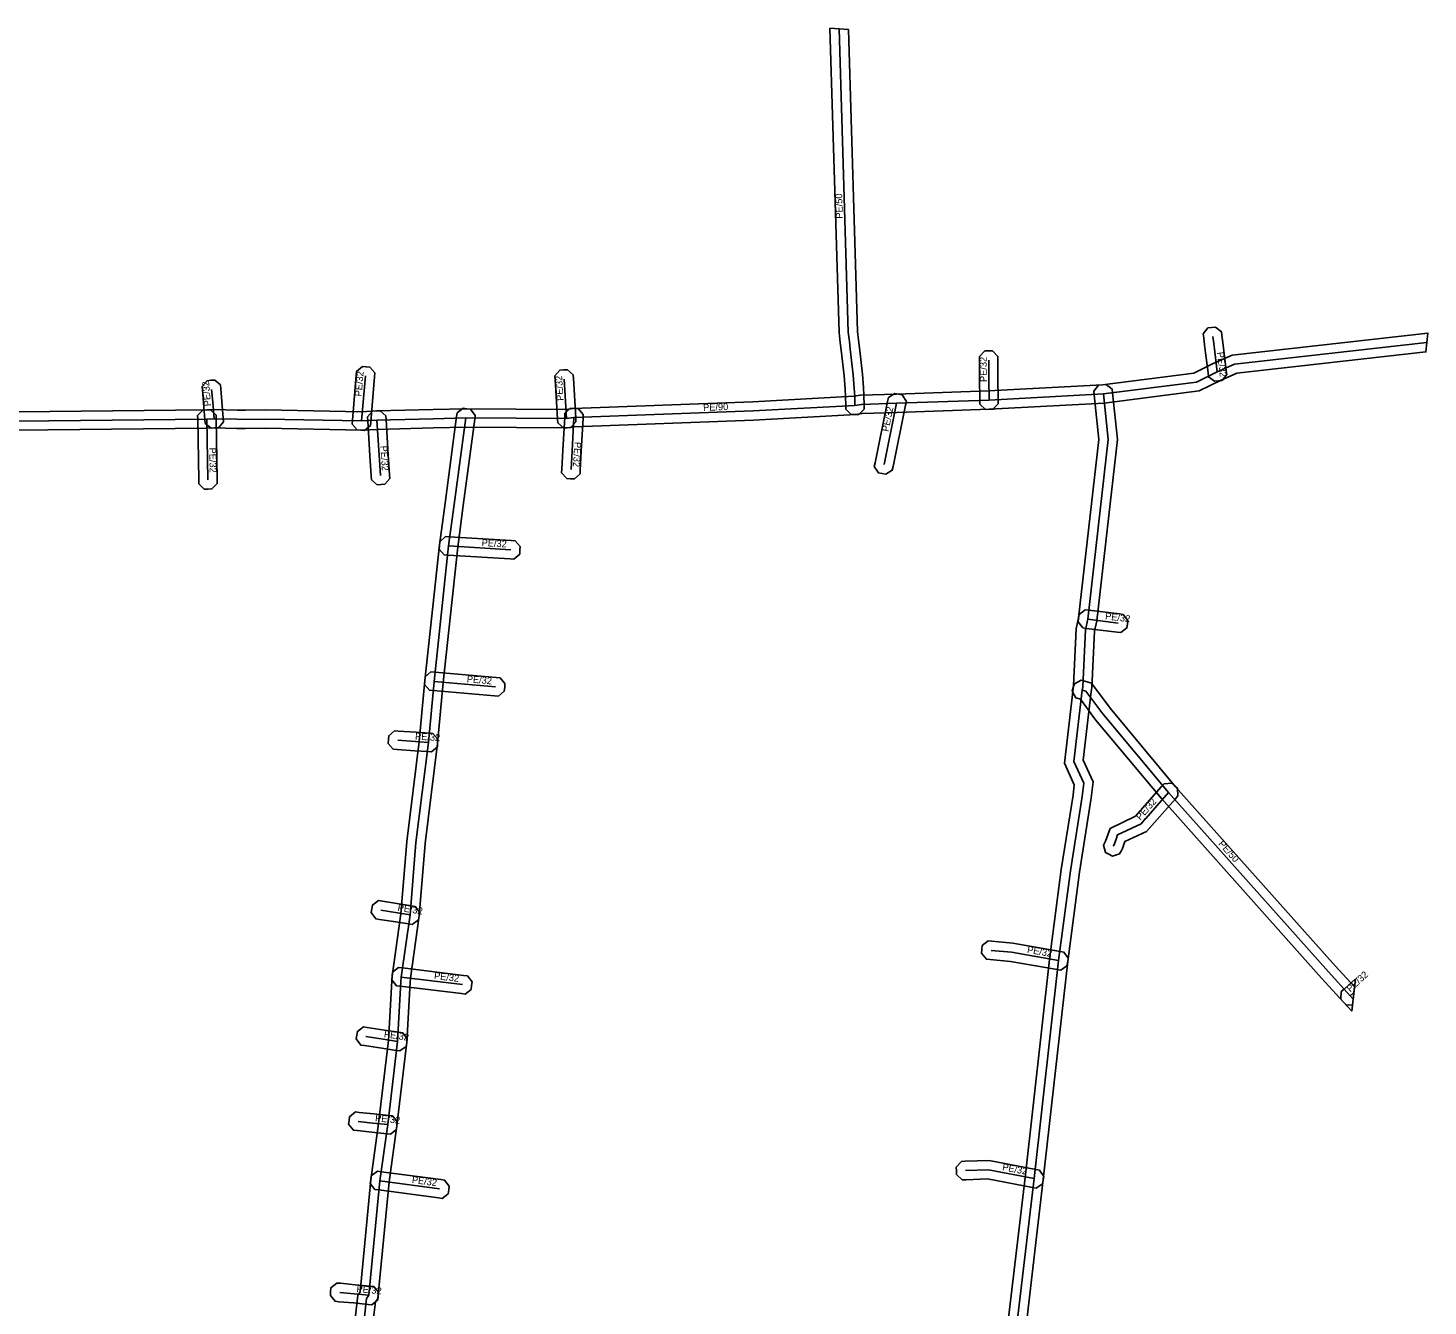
# Model space of a CAD drawing. Extents: x -772893 to -772575, y -1033735 to -1033288.
# Drawn here: x -772727.1 to -772574.9, y -1033442.7 to -1033303.8 of the extents above; entities that cross this region are included whole.
import ezdxf

# ---------------------------------------------------------------- set-up
doc = ezdxf.new("R2010")
doc.units = 0
for name, color, linetype in [('1', 7, 'Continuous'), ('24', 7, 'Continuous'), ('30', 7, 'Continuous')]:
    doc.layers.add(name, color=color, linetype=linetype)

msp = doc.modelspace()

# ---------------------------------------------------------------- linework, layer by layer
at = {"layer": '1'}
for points in [[(-772639.94, -1033303.76), (-772637.94, -1033303.91), (-772636.95, -1033336.73), (-772636.84, -1033337.7), (-772636.74, -1033338.53), (-772636.41, -1033341.38), (-772636.3, -1033342.85), (-772636.24, -1033343.72), (-772636.23, -1033344.77), (-772636.23, -1033345.19), (-772636.81, -1033345.78), (-772637.22, -1033345.78), (-772637.64, -1033345.78), (-772638.23, -1033345.2), (-772638.23, -1033344.79), (-772638.24, -1033343.8), (-772638.3, -1033343.01), (-772638.41, -1033341.56), (-772638.72, -1033338.77), (-772638.82, -1033337.94), (-772638.95, -1033336.87)], [(-772598.79, -1033341.66), (-772598.84, -1033341.24), (-772599.11, -1033339.08), (-772599.23, -1033338.18), (-772599.32, -1033337.42), (-772599.37, -1033337.01), (-772598.86, -1033336.36), (-772598.45, -1033336.31), (-772598.04, -1033336.26), (-772597.39, -1033336.77), (-772597.34, -1033337.18), (-772597.24, -1033337.94), (-772597.13, -1033338.83), (-772596.86, -1033340.99), (-772596.81, -1033341.41), (-772597.31, -1033342.06), (-772597.72, -1033342.11), (-772598.14, -1033342.16)], [(-772623.65, -1033344.63), (-772623.65, -1033344.21), (-772623.68, -1033341.8), (-772623.68, -1033340.71), (-772623.68, -1033339.86), (-772623.68, -1033339.45), (-772623.09, -1033338.86), (-772622.68, -1033338.86), (-772622.27, -1033338.86), (-772621.68, -1033339.45), (-772621.68, -1033339.86), (-772621.68, -1033340.71), (-772621.68, -1033341.78), (-772621.65, -1033344.19), (-772621.65, -1033344.6), (-772622.22, -1033345.2), (-772622.64, -1033345.2), (-772623.05, -1033345.21)], [(-772691.87, -1033346.8), (-772691.84, -1033346.39), (-772691.43, -1033341.49), (-772691.39, -1033341.08), (-772690.76, -1033340.55), (-772690.35, -1033340.58), (-772689.94, -1033340.61), (-772689.4, -1033341.25), (-772689.43, -1033341.66), (-772689.84, -1033346.55), (-772689.88, -1033346.97), (-772690.51, -1033347.5), (-772690.92, -1033347.47), (-772691.34, -1033347.43)], [(-772707.83, -1033346.73), (-772707.87, -1033346.31), (-772708.02, -1033344.51), (-772708.14, -1033343.14), (-772708.17, -1033342.72), (-772707.64, -1033342.09), (-772707.22, -1033342.05), (-772706.81, -1033342.02), (-772706.18, -1033342.55), (-772706.14, -1033342.96), (-772706.03, -1033344.34), (-772705.87, -1033346.15), (-772705.84, -1033346.56), (-772706.37, -1033347.19), (-772706.79, -1033347.23), (-772707.2, -1033347.26)], [(-772669.53, -1033346.68), (-772669.56, -1033346.27), (-772669.71, -1033343.79), (-772669.82, -1033341.98), (-772669.84, -1033341.57), (-772669.29, -1033340.95), (-772668.88, -1033340.92), (-772668.47, -1033340.9), (-772667.85, -1033341.45), (-772667.82, -1033341.86), (-772667.71, -1033343.67), (-772667.56, -1033346.15), (-772667.54, -1033346.56), (-772668.09, -1033347.18), (-772668.5, -1033347.21), (-772668.91, -1033347.23)], [(-772635.12, -1033351.42), (-772635.04, -1033351.01), (-772633.67, -1033344.34), (-772633.59, -1033343.93), (-772632.9, -1033343.48), (-772632.49, -1033343.56), (-772632.08, -1033343.64), (-772631.63, -1033344.34), (-772631.71, -1033344.74), (-772633.08, -1033351.41), (-772633.16, -1033351.82), (-772633.85, -1033352.27), (-772634.26, -1033352.19), (-772634.67, -1033352.11)], [(-772706.66, -1033345.84), (-772706.65, -1033346.25), (-772706.54, -1033352.85), (-772706.53, -1033353.27), (-772707.11, -1033353.86), (-772707.52, -1033353.87), (-772707.94, -1033353.88), (-772708.53, -1033353.3), (-772708.54, -1033352.89), (-772708.65, -1033346.29), (-772708.66, -1033345.87), (-772708.08, -1033345.28), (-772707.67, -1033345.27), (-772707.25, -1033345.26)], [(-772666.75, -1033345.75), (-772666.77, -1033346.17), (-772666.97, -1033349.77), (-772667.08, -1033351.81), (-772667.1, -1033352.22), (-772667.72, -1033352.77), (-772668.14, -1033352.75), (-772668.55, -1033352.73), (-772669.1, -1033352.11), (-772669.08, -1033351.7), (-772668.97, -1033349.66), (-772668.77, -1033346.06), (-772668.75, -1033345.64), (-772668.13, -1033345.09), (-772667.71, -1033345.11), (-772667.3, -1033345.13)], [(-772688.21, -1033345.91), (-772688.18, -1033346.32), (-772687.95, -1033350.14), (-772687.8, -1033352.31), (-772687.77, -1033352.72), (-772688.32, -1033353.35), (-772688.73, -1033353.38), (-772689.14, -1033353.41), (-772689.77, -1033352.86), (-772689.8, -1033352.45), (-772689.95, -1033350.26), (-772690.18, -1033346.44), (-772690.2, -1033346.03), (-772689.65, -1033345.41), (-772689.24, -1033345.38), (-772688.83, -1033345.36)], [(-772681.73, -1033359.04), (-772681.32, -1033359.06), (-772674.57, -1033359.46), (-772674.16, -1033359.49), (-772673.61, -1033360.11), (-772673.63, -1033360.52), (-772673.66, -1033360.93), (-772674.28, -1033361.48), (-772674.69, -1033361.46), (-772681.44, -1033361.06), (-772681.85, -1033361.03), (-772682.4, -1033360.41), (-772682.38, -1033360), (-772682.35, -1033359.59)], [(-772612.21, -1033366.99), (-772611.8, -1033367.04), (-772608.48, -1033367.44), (-772608.07, -1033367.49), (-772607.56, -1033368.14), (-772607.61, -1033368.55), (-772607.66, -1033368.96), (-772608.31, -1033369.47), (-772608.72, -1033369.42), (-772612.04, -1033369.02), (-772612.45, -1033368.97), (-772612.96, -1033368.32), (-772612.91, -1033367.91), (-772612.86, -1033367.5)], [(-772683.3, -1033373.75), (-772682.89, -1033373.78), (-772676.2, -1033374.35), (-772675.79, -1033374.39), (-772675.26, -1033375.02), (-772675.29, -1033375.44), (-772675.33, -1033375.85), (-772675.96, -1033376.38), (-772676.38, -1033376.35), (-772683.06, -1033375.78), (-772683.47, -1033375.74), (-772684, -1033375.11), (-772683.97, -1033374.7), (-772683.93, -1033374.28)], [(-772582.93, -1033407.98), (-772583.22, -1033410.62), (-772584.12, -1033409.64), (-772586.51, -1033407.03), (-772603.9, -1033387.52), (-772611.06, -1033378.94), (-772612.72, -1033376.72), (-772612.81, -1033376.69), (-772613.21, -1033376.57), (-772613.61, -1033375.85), (-772613.49, -1033375.45), (-772613.37, -1033375.05), (-772612.65, -1033374.65), (-772612.25, -1033374.77), (-772611.52, -1033374.98), (-772609.48, -1033377.7), (-772602.38, -1033386.22), (-772585.03, -1033405.69)], [(-772683.24, -1033382.44), (-772683.65, -1033382.41), (-772685.06, -1033382.31), (-772686.99, -1033382.18), (-772687.4, -1033382.15), (-772687.95, -1033381.52), (-772687.92, -1033381.11), (-772687.89, -1033380.69), (-772687.26, -1033380.15), (-772686.85, -1033380.18), (-772684.92, -1033380.31), (-772683.51, -1033380.41), (-772683.1, -1033380.44), (-772682.55, -1033381.07), (-772682.58, -1033381.48), (-772682.61, -1033381.89)], [(-772602.12, -1033387.22), (-772602.39, -1033387.53), (-772605.52, -1033391.08), (-772607.88, -1033392.19), (-772608.14, -1033392.94), (-772608.26, -1033393.16), (-772608.45, -1033393.53), (-772609.24, -1033393.77), (-772609.61, -1033393.57), (-772609.98, -1033393.38), (-772610.22, -1033392.59), (-772610.02, -1033392.22), (-772609.98, -1033392.14), (-772609.5, -1033390.75), (-772606.74, -1033389.44), (-772603.89, -1033386.21), (-772603.62, -1033385.9), (-772602.79, -1033385.85), (-772602.48, -1033386.12), (-772602.17, -1033386.39)], [(-772685.33, -1033401.2), (-772685.74, -1033401.14), (-772687.11, -1033400.92), (-772688.9, -1033400.64), (-772689.31, -1033400.57), (-772689.79, -1033399.9), (-772689.73, -1033399.49), (-772689.66, -1033399.09), (-772688.99, -1033398.6), (-772688.58, -1033398.66), (-772686.8, -1033398.95), (-772685.42, -1033399.16), (-772685.02, -1033399.23), (-772684.53, -1033399.9), (-772684.59, -1033400.31), (-772684.66, -1033400.71)], [(-772614.85, -1033406.17), (-772615.26, -1033406.09), (-772620.33, -1033405.21), (-772622.52, -1033405.01), (-772622.94, -1033404.97), (-772623.46, -1033404.33), (-772623.43, -1033403.92), (-772623.39, -1033403.5), (-772622.75, -1033402.97), (-772622.34, -1033403.01), (-772620.07, -1033403.23), (-772614.92, -1033404.12), (-772614.51, -1033404.2), (-772614.03, -1033404.87), (-772614.1, -1033405.28), (-772614.18, -1033405.69)], [(-772686.82, -1033405.87), (-772686.41, -1033405.92), (-772679.75, -1033406.73), (-772679.34, -1033406.78), (-772678.83, -1033407.43), (-772678.88, -1033407.84), (-772678.93, -1033408.25), (-772679.58, -1033408.76), (-772679.99, -1033408.71), (-772686.65, -1033407.9), (-772687.06, -1033407.85), (-772687.57, -1033407.2), (-772687.52, -1033406.79), (-772687.47, -1033406.38)], [(-772582.83, -1033407.1), (-772583.15, -1033409.97), (-772583.84, -1033409.94), (-772584.12, -1033409.63), (-772584.4, -1033409.33), (-772584.36, -1033408.5), (-772584.05, -1033408.22)], [(-772686.67, -1033414.95), (-772687.08, -1033414.89), (-772688.66, -1033414.65), (-772690.52, -1033414.37), (-772690.93, -1033414.31), (-772691.42, -1033413.64), (-772691.35, -1033413.23), (-772691.29, -1033412.82), (-772690.63, -1033412.33), (-772690.22, -1033412.39), (-772688.37, -1033412.67), (-772686.78, -1033412.91), (-772686.37, -1033412.97), (-772685.88, -1033413.64), (-772685.94, -1033414.05), (-772686, -1033414.46)], [(-772687.69, -1033423.99), (-772688.11, -1033423.94), (-772689.73, -1033423.77), (-772691.32, -1033423.6), (-772691.73, -1033423.56), (-772692.25, -1033422.92), (-772692.2, -1033422.51), (-772692.16, -1033422.09), (-772691.52, -1033421.57), (-772691.1, -1033421.62), (-772689.52, -1033421.78), (-772687.89, -1033421.96), (-772687.48, -1033422), (-772686.96, -1033422.64), (-772687.01, -1033423.06), (-772687.05, -1033423.47)], [(-772617.52, -1033429.87), (-772617.93, -1033429.79), (-772622.8, -1033428.86), (-772625.17, -1033428.94), (-772625.58, -1033428.95), (-772626.19, -1033428.39), (-772626.2, -1033427.97), (-772626.21, -1033427.56), (-772625.65, -1033426.95), (-772625.23, -1033426.94), (-772622.64, -1033426.86), (-772617.55, -1033427.83), (-772617.15, -1033427.91), (-772616.68, -1033428.59), (-772616.76, -1033429), (-772616.83, -1033429.4)], [(-772689.13, -1033428.01), (-772688.72, -1033428.07), (-772682.23, -1033428.93), (-772681.82, -1033428.98), (-772681.31, -1033429.64), (-772681.37, -1033430.05), (-772681.42, -1033430.46), (-772682.08, -1033430.97), (-772682.49, -1033430.91), (-772688.98, -1033430.05), (-772689.39, -1033430), (-772689.9, -1033429.34), (-772689.84, -1033428.93), (-772689.79, -1033428.52)], [(-772689.72, -1033442.54), (-772690.14, -1033442.5), (-772691.73, -1033442.34), (-772693.3, -1033442.2), (-772693.72, -1033442.16), (-772694.24, -1033441.52), (-772694.21, -1033441.11), (-772694.17, -1033440.69), (-772693.53, -1033440.17), (-772693.12, -1033440.2), (-772691.55, -1033440.35), (-772689.95, -1033440.5), (-772689.53, -1033440.54), (-772689.01, -1033441.18), (-772689.04, -1033441.59), (-772689.08, -1033442.01)]]:
    msp.add_lwpolyline(points, close=True, dxfattribs=at)
for points in [[(-772731.57, -1033345.52), (-772707.68, -1033345.27), (-772706.88, -1033345.23), (-772704.38, -1033345.29), (-772703.45, -1033345.3), (-772701.27, -1033345.26), (-772690.86, -1033345.47), (-772689.22, -1033345.38), (-772683.08, -1033345.23), (-772679.54, -1033345.14), (-772668.62, -1033345.21), (-772667.85, -1033345.11), (-772648.33, -1033344.38), (-772637.33, -1033343.78), (-772636.6, -1033343.67), (-772632.72, -1033343.54), (-772622.69, -1033343.2), (-772610.31, -1033342.53), (-772600.39, -1033341.27), (-772598.28, -1033340.21), (-772596.24, -1033339.31), (-772574.94, -1033336.92), (-772575.17, -1033338.96), (-772595.71, -1033341.27), (-772597.42, -1033342.03), (-772599.8, -1033343.21), (-772610.13, -1033344.53), (-772622.61, -1033345.2), (-772632.66, -1033345.54), (-772636.42, -1033345.67), (-772637.13, -1033345.78), (-772648.23, -1033346.38), (-772667.69, -1033347.11), (-772668.5, -1033347.21), (-772679.52, -1033347.14), (-772683.02, -1033347.23), (-772689.14, -1033347.38), (-772690.82, -1033347.47), (-772701.27, -1033347.26), (-772703.45, -1033347.3), (-772704.42, -1033347.29), (-772706.86, -1033347.23), (-772707.62, -1033347.27), (-772731.89, -1033347.52)], [(-772620.68, -1033445.19), (-772618.73, -1033428.7), (-772616.08, -1033404.99), (-772614.8, -1033395.22), (-772613.51, -1033387.14), (-772613.38, -1033386.01), (-772614.46, -1033383.66), (-772613.52, -1033375.59), (-772613.47, -1033375.27), (-772613.16, -1033369.06), (-772612.91, -1033367.87), (-772610.7, -1033348.49), (-772611.21, -1033343.64), (-772611.26, -1033343.22), (-772610.74, -1033342.58), (-772610.33, -1033342.54), (-772609.91, -1033342.49), (-772609.27, -1033343.01), (-772609.23, -1033343.42), (-772608.68, -1033348.49), (-772610.93, -1033368.19), (-772611.17, -1033369.32), (-772611.47, -1033375.49), (-772611.54, -1033375.87), (-772612.4, -1033383.34), (-772611.32, -1033385.69), (-772611.53, -1033387.42), (-772612.82, -1033395.5), (-772614.1, -1033405.23), (-772616.75, -1033428.92), (-772618.7, -1033445.43)], [(-772691.52, -1033443.73), (-772691.26, -1033441.49), (-772691.01, -1033441.14), (-772689.84, -1033428.94), (-772688.99, -1033422.82), (-772687.93, -1033413.81), (-772687.57, -1033407.35), (-772687.53, -1033406.8), (-772686.57, -1033400.04), (-772685.94, -1033392.18), (-772684.57, -1033381.3), (-772683.96, -1033374.68), (-772682.37, -1033359.94), (-772681.77, -1033355.41), (-772680.52, -1033346), (-772680.47, -1033345.59), (-772679.81, -1033345.09), (-772679.4, -1033345.14), (-772678.99, -1033345.2), (-772678.49, -1033345.86), (-772678.54, -1033346.27), (-772679.79, -1033355.67), (-772680.39, -1033360.18), (-772681.97, -1033374.88), (-772682.59, -1033381.52), (-772683.95, -1033392.38), (-772684.59, -1033400.26), (-772685.54, -1033407.02), (-772685.57, -1033407.49), (-772685.93, -1033413.99), (-772687.01, -1033423.08), (-772687.86, -1033429.18), (-772689.07, -1033441.86), (-772689.34, -1033442.23), (-772689.54, -1033443.95)]]:
    msp.add_lwpolyline(points, dxfattribs=at)
at = {"layer": '24'}
for points in [[(-772637.23, -1033344.78), (-772637.24, -1033343.76), (-772637.3, -1033342.93), (-772637.41, -1033341.47), (-772637.73, -1033338.65), (-772637.83, -1033337.82), (-772637.95, -1033336.8), (-772638.94, -1033303.83)], [(-772597.85, -1033341.12), (-772598.12, -1033338.95), (-772598.23, -1033338.06), (-772598.33, -1033337.3)], [(-772575.05, -1033337.94), (-772595.98, -1033340.29), (-772597.85, -1033341.12), (-772600.09, -1033342.24), (-772610.22, -1033343.53), (-772622.65, -1033344.2), (-772632.69, -1033344.54), (-772636.51, -1033344.67), (-772637.23, -1033344.78), (-772648.28, -1033345.38), (-772667.77, -1033346.11), (-772668.56, -1033346.21), (-772679.53, -1033346.14), (-772683.05, -1033346.23), (-772689.18, -1033346.38), (-772690.84, -1033346.47), (-772701.27, -1033346.26), (-772703.45, -1033346.3), (-772704.4, -1033346.29), (-772706.87, -1033346.23), (-772707.65, -1033346.27), (-772731.73, -1033346.52), (-772732.5, -1033346.26)], [(-772622.65, -1033344.2), (-772622.68, -1033341.79), (-772622.68, -1033340.71), (-772622.68, -1033339.86)], [(-772690.84, -1033346.47), (-772690.43, -1033341.58)], [(-772668.56, -1033346.21), (-772668.71, -1033343.73), (-772668.82, -1033341.92)], [(-772706.87, -1033346.23), (-772707.02, -1033344.42), (-772707.14, -1033343.05)], [(-772610.22, -1033343.53), (-772609.69, -1033348.49), (-772611.92, -1033368.03), (-772612.16, -1033369.19), (-772612.47, -1033375.38), (-772612.53, -1033375.73), (-772613.43, -1033383.5), (-772612.35, -1033385.85), (-772612.52, -1033387.28), (-772613.81, -1033395.36), (-772615.09, -1033405.11), (-772617.74, -1033428.81), (-772619.69, -1033445.31)], [(-772634.06, -1033351.21), (-772632.69, -1033344.54)], [(-772707.65, -1033346.27), (-772707.54, -1033352.87)], [(-772679.53, -1033346.14), (-772680.78, -1033355.54), (-772681.38, -1033360.06), (-772682.97, -1033374.78), (-772683.58, -1033381.41), (-772684.94, -1033392.28), (-772685.58, -1033400.15), (-772686.53, -1033406.91), (-772686.57, -1033407.42), (-772686.93, -1033413.9), (-772688, -1033422.95), (-772688.85, -1033429.06), (-772690.04, -1033441.5), (-772690.3, -1033441.86), (-772690.53, -1033443.84)], [(-772689.18, -1033346.38), (-772688.95, -1033350.2), (-772688.8, -1033352.38)], [(-772667.77, -1033346.11), (-772667.97, -1033349.71), (-772668.08, -1033351.75)], [(-772681.38, -1033360.06), (-772674.63, -1033360.46)], [(-772611.92, -1033368.03), (-772608.6, -1033368.43)], [(-772682.97, -1033374.78), (-772676.29, -1033375.35)], [(-772612.53, -1033375.73), (-772612.12, -1033375.85), (-772610.27, -1033378.32), (-772603.14, -1033386.87), (-772585.77, -1033406.36), (-772583.38, -1033408.96), (-772583.07, -1033409.3)], [(-772683.58, -1033381.41), (-772684.99, -1033381.31), (-772686.92, -1033381.18)], [(-772603.14, -1033386.87), (-772605.62, -1033389.68), (-772605.63, -1033389.69), (-772606.13, -1033390.26), (-772608.69, -1033391.47), (-772608.75, -1033391.65), (-772608.77, -1033391.7), (-772609.06, -1033392.54), (-772609.14, -1033392.69)], [(-772685.58, -1033400.15), (-772686.95, -1033399.93), (-772688.74, -1033399.65)], [(-772615.09, -1033405.11), (-772620.2, -1033404.22), (-772622.43, -1033404.01)], [(-772686.53, -1033406.91), (-772679.87, -1033407.72)], [(-772583.38, -1033408.96), (-772583, -1033408.61)], [(-772686.93, -1033413.9), (-772688.51, -1033413.66), (-772690.37, -1033413.38)], [(-772688, -1033422.95), (-772689.62, -1033422.78), (-772691.21, -1033422.61)], [(-772617.74, -1033428.81), (-772622.72, -1033427.86), (-772625.2, -1033427.94)], [(-772688.85, -1033429.06), (-772682.36, -1033429.92)], [(-772690.04, -1033441.5), (-772691.64, -1033441.35), (-772693.21, -1033441.2)]]:
    msp.add_lwpolyline(points, dxfattribs=at)

# ---------------------------------------------------------------- texts
at = {"layer": '30'}
for s, rotation, p in [('PE/50', 91.7165, (-772638.53, -1033324.47)), ('PE/32', 277.1413, (-772597.89, -1033339.01)), ('PE/32', 90.6888, (-772622.88, -1033342.23)), ('PE/32', 94.7977, (-772707.2, -1033344.84)), ('PE/32', 85.2228, (-772690.84, -1033343.82)), ('PE/32', 93.4369, (-772668.89, -1033344.26)), ('PE/90', 2.145, (-772653.71, -1033345.38)), ('PE/32', 78.393, (-772633.58, -1033347.68)), ('PE/32', 270.9548, (-772707.4, -1033349.37)), ('PE/32', 273.4614, (-772688.8, -1033349.18)), ('PE/32', 266.8669, (-772667.72, -1033348.73)), ('PE/32', 356.6087, (-772677.81, -1033360.06)), ('PE/32', 353.13, (-772610.06, -1033368.03)), ('PE/32', 355.1228, (-772679.43, -1033374.87)), ('PE/32', 356.0365, (-772685.05, -1033381.09)), ('PE/32', 48.593, (-772606.2, -1033389.92)), ('PE/50', 311.7083, (-772597.77, -1033392.47)), ('PE/32', 351.0372, (-772686.96, -1033399.7)), ('PE/32', 350.12, (-772618.55, -1033404.27)), ('PE/32', 353.0657, (-772683, -1033407.12)), ('PE/32', 42.3233, (-772583.39, -1033408.59)), ('PE/32', 351.4632, (-772688.45, -1033413.44)), ('PE/32', 353.9045, (-772689.4, -1033422.58)), ('PE/32', 349.1998, (-772621.25, -1033427.9)), ('PE/32', 352.4516, (-772685.41, -1033429.29)), ('PE/32', 354.5377, (-772691.42, -1033441.15))]:
    msp.add_text(s, height=0.75, rotation=rotation, dxfattribs=at).set_placement(p)

doc.saveas('drawing.dxf')
